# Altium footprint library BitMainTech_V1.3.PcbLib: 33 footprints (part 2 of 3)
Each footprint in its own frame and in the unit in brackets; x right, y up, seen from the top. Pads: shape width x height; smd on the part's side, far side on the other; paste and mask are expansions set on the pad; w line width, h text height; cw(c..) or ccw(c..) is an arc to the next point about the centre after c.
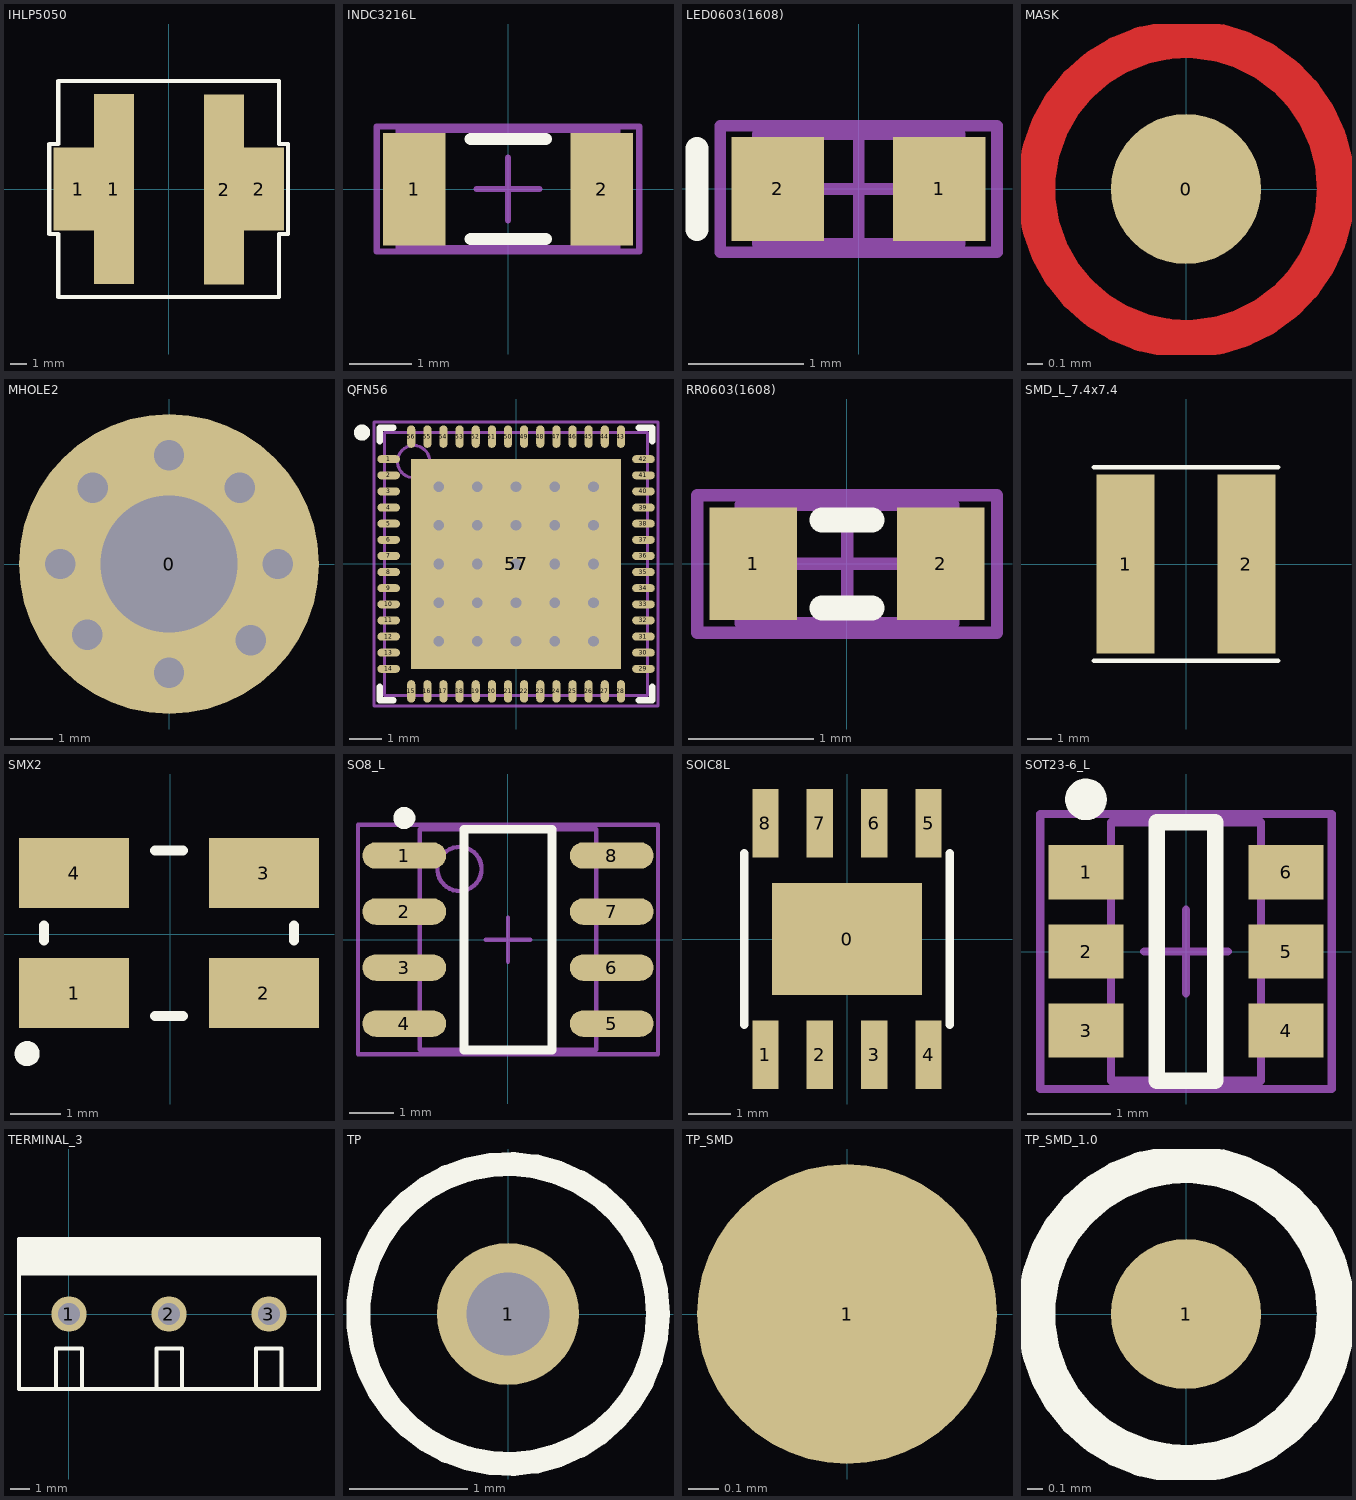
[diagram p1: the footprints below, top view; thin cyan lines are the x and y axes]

## IHLP5050 [mm]
height 18.15
pads (4):
  rect 2.945x4.95 smd: 1(-5.407,0) 2(5.407,0)
  rect 2.388x11.328 smd: 1(-3.28,0) 2(3.32,-0.03)
Top Overlay:
  lines w0.254: -7.137,-2.688 -6.6,-2.688 -6.6,-3.225 -6.6,-6.45 6.6,-6.45 6.6,-3.225 6.6,-2.688 7.137,-2.688 7.137,2.688 6.6,2.688 6.6,3.225 6.6,6.45 -6.6,6.45 -6.6,3.225 -6.6,2.688 -7.137,2.688 -7.137,-2.688
Top Paste:
  rectangle: 2.134,-5.664 4.521,5.664
  rectangle: -4.521,-5.664 -2.134,5.664
Top Solder:
  rectangle: 2.134,-5.664 4.521,5.664
  rectangle: -4.521,-5.664 -2.134,5.664
3D body: height 6.5, standoff 0, extent -6.6,-6.449 6.6,6.449

## INDC3216L [mm] "Chip Inductor, Body 3.2x1.6mm, IPC High Density"
height 1.9
pads (2):
  rect 1x1.8 smd: 1(-1.5,0) 2(1.5,0)
Top Overlay:
  lines w0.2: -0.6,-0.8 0.6,-0.8 ; -0.6,0.8 0.6,0.8
Mechanical 13:
  lines w0.1: -1.75,-0.95 1.75,-0.95 1.75,0.95 -1.75,0.95 -1.75,-0.95
Mechanical 15:
  lines w0.1: -0.5,0 0.5,0 ; 0,-0.5 0,0.5 ; -2.1,-1 2.1,-1 2.1,1 -2.1,1 -2.1,-1
3D body: height 1.9, standoff 0, extent -1.75,-0.95 1.75,0.95

## LED0603(1608) [mm] "Chip LED, Body 1.6x0.8mm, IPC High Density"
height 18.15
pads (2):
  rect 0.8x0.9 smd: 1(0.7,0) 2(-0.7,0)
Top Overlay:
  lines w0.2: -1.4,-0.35 -1.4,0.35
Mechanical 13:
  lines w0.1: -0.875,-0.475 0.875,-0.475 0.875,0.475 -0.875,0.475 -0.875,-0.475
Mechanical 15:
  lines w0.1: -0.475,0 0.475,0 ; 0,-0.475 0,0.475 ; -1.2,-0.55 1.2,-0.55 1.2,0.55 -1.2,0.55 -1.2,-0.55
3D body: height 0.85, standoff 0, extent -0.875,-0.475 0.875,0.475

## MASK [mm] "SMD MASK 1mm"
height 18.15
pads (1):
  round 1 smd: 0(0,0)
Top Layer:
  circle w0.254: c0,0 r1
Top Paste:
  circle w1.5: c0,0 r0.508
  circle w0.254: c0,0 r0.508
Top Solder:
  circle w1: c0,0 r0.762

## MHOLE2 [mm]
height 0.9
pads (1):
  round 7 hole 3.2 unplated: 0(0,0)
via 1.905,-1.778 diameter 1.27 hole 0.711
via 1.651,1.778 diameter 1.27 hole 0.711
via -1.778,1.778 diameter 1.27 hole 0.711
via -1.905,-1.651 diameter 1.27 hole 0.711
via 0,-2.54 diameter 1.27 hole 0.711
via -2.54,0 diameter 1.27 hole 0.711
via 2.54,0 diameter 1.27 hole 0.711
via 0,2.54 diameter 1.27 hole 0.711

## QFN56 [mm]
height 18.15
pads (58):
  oval 0.7x0.25 smd: 1(-3.95,3.25) 2(-3.95,2.75) 3(-3.95,2.25) 4(-3.95,1.75) 5(-3.95,1.25) 6(-3.95,0.75) 7(-3.95,0.25) 8(-3.95,-0.25) 9(-3.95,-0.75) 10(-3.95,-1.25) 11(-3.95,-1.75) 12(-3.95,-2.25) 13(-3.95,-2.75) 14(-3.95,-3.25) 29(3.95,-3.25) 30(3.95,-2.75) 31(3.95,-2.25) 32(3.95,-1.75) 33(3.95,-1.25) 34(3.95,-0.75) 35(3.95,-0.25) 36(3.95,0.25) 37(3.95,0.75) 38(3.95,1.25) 39(3.95,1.75) 40(3.95,2.25) 41(3.95,2.75) 42(3.95,3.25)
  oval 0.25x0.7 smd: 15(-3.25,-3.95) 16(-2.75,-3.95) 17(-2.25,-3.95) 18(-1.75,-3.95) 19(-1.25,-3.95) 20(-0.75,-3.95) 21(-0.25,-3.95) 22(0.25,-3.95) 23(0.75,-3.95) 24(1.25,-3.95) 25(1.75,-3.95) 26(2.25,-3.95) 27(2.75,-3.95) 28(3.25,-3.95) 43(3.25,3.95) 44(2.75,3.95) 45(2.25,3.95) 46(1.75,3.95) 47(1.25,3.95) 48(0.75,3.95) 49(0.25,3.95) 50(-0.25,3.95) 51(-0.75,3.95) 52(-1.25,3.95) 53(-1.75,3.95) 54(-2.25,3.95) 55(-2.75,3.95) 56(-3.25,3.95)
  rect 6.5x6.5 smd: 57(0,0)
  rect 6.5x6.5 smd far side: 57(0,0)
via -2.4,2.4 diameter 0.66 hole 0.33
via -1.2,2.4 diameter 0.66 hole 0.33
via 0,2.4 diameter 0.66 hole 0.33
via 1.2,2.4 diameter 0.66 hole 0.33
via 2.4,2.4 diameter 0.66 hole 0.33
via -2.4,1.2 diameter 0.66 hole 0.33
via -1.2,1.2 diameter 0.66 hole 0.33
via 0,1.2 diameter 0.66 hole 0.33
via 1.2,1.2 diameter 0.66 hole 0.33
via 2.4,1.2 diameter 0.66 hole 0.33
via -2.4,0 diameter 0.66 hole 0.33
via -1.2,0 diameter 0.66 hole 0.33
via 0,0 diameter 0.66 hole 0.33
via 1.2,0 diameter 0.66 hole 0.33
via 2.4,0 diameter 0.66 hole 0.33
via -2.4,-1.2 diameter 0.66 hole 0.33
via -1.2,-1.2 diameter 0.66 hole 0.33
via 0,-1.2 diameter 0.66 hole 0.33
via 1.2,-1.2 diameter 0.66 hole 0.33
via 2.4,-1.2 diameter 0.66 hole 0.33
via -2.4,-2.4 diameter 0.66 hole 0.33
via -1.2,-2.4 diameter 0.66 hole 0.33
via 0,-2.4 diameter 0.66 hole 0.33
via 1.2,-2.4 diameter 0.66 hole 0.33
via 2.4,-2.4 diameter 0.66 hole 0.33
Top Overlay:
  circle w0.25: c-4.775,4.075 r0.125
  lines w0.2: -4.225,-3.8 -4.225,-4.225 -3.8,-4.225 ; -4.225,3.8 -4.225,4.225 -3.8,4.225 ; 3.8,-4.225 4.225,-4.225 4.225,-3.8 ; 3.8,4.225 4.225,4.225 4.225,3.8
Mechanical 13:
  circle w0.1: c-3.175,3.175 r0.5
  lines w0.1: -4.075,-4.075 -4.075,4.075 4.075,4.075 4.075,-4.075 -4.075,-4.075
Mechanical 15:
  lines w0.1: -0.5,0 0.5,0 ; 0,-0.5 0,0.5 ; -4.4,-4.4 -4.4,4.4 4.4,4.4 4.4,-4.4 -4.4,-4.4
3D body: height 0.9, standoff 0, extent -4.075,-4.075 4.075,4.075

## RR0603(1608) [mm] "Chip Resistor, Body 1.6x0.8mm, IPC High Density"
height 0.6
pads (2):
  rect 0.7x0.9 smd: 1(-0.75,0) 2(0.75,0)
Top Overlay:
  lines w0.2: -0.2,-0.35 0.2,-0.35 ; -0.2,0.35 0.2,0.35
Mechanical 13:
  lines w0.1: -0.85,-0.475 -0.85,0.475 0.85,0.475 0.85,-0.475 -0.85,-0.475
Mechanical 15:
  lines w0.1: -0.475,0 0.475,0 ; 0,-0.475 0,0.475 ; -1.2,-0.55 -1.2,0.55 1.2,0.55 1.2,-0.55 -1.2,-0.55
3D body: height 0.6, standoff 0, extent -0.85,-0.475 0.85,0.475

## SMD_L_7.4x7.4 [mm]
height 18.15
pads (2):
  rect 2.4x7.4 smd: 1(-2.5,0) 2(2.5,0)
Top Overlay:
  lines w0.203: -3.8,-4 3.8,-4 ; -3.8,4 3.8,4

## SMX2 [mm]
height 0.9
pads (4):
  rect 2.2x1.4 smd: 1(-1.925,-1.175) 2(1.875,-1.175) 3(1.875,1.225) 4(-1.925,1.225)
Top Overlay:
  circle w0.25: c-2.862,-2.384 r0.125
  lines w0.2: -2.525,-0.125 -2.525,0.175 ; -0.304,-1.628 0.254,-1.628 ; -0.304,1.678 0.254,1.678 ; 2.475,-0.125 2.475,0.175

## SO8_L [mm] "SOIC, 8-Leads, Body 4.9x3.9mm, Pitch 1.27mm, IPC High Density"
height 1.75
pads (8):
  oval 1.9x0.6 smd: 1(-2.35,1.905) 2(-2.35,0.635) 3(-2.35,-0.635) 4(-2.35,-1.905) 5(2.35,-1.905) 6(2.35,-0.635) 7(2.35,0.635) 8(2.35,1.905)
Top Overlay:
  circle w0.25: c-2.35,2.755 r0.125
  lines w0.2: -1,-2.5 1,-2.5 1,2.5 -1,2.5 -1,-2.5
Mechanical 13:
  circle w0.1: c-1.1,1.6 r0.5
  lines w0.1: -2,-2.5 2,-2.5 2,2.5 -2,2.5 -2,-2.5
Mechanical 15:
  lines w0.1: -0.5,0 0.5,0 ; 0,-0.5 0,0.5 ; -3.4,-2.6 3.4,-2.6 3.4,2.6 -3.4,2.6 -3.4,-2.6
3D body: height 1.75, standoff 0, extent -2,-2.5 2,2.5

## SOIC8L [mm]
pads (9):
  rect 3.51x2.62 smd: 0(0,0)
  rect 0.61x1.6 smd: 1(-1.905,-2.7) 2(-0.635,-2.7) 3(0.635,-2.7) 4(1.905,-2.7) 5(1.905,2.7) 6(0.635,2.7) 7(-0.635,2.7) 8(-1.905,2.7)
Top Overlay:
  lines w0.203: -2.4,-2 -2.4,2 ; 2.4,-2 2.4,2

## SOT23-6_L [mm] "SOT23, 6-Leads, Body 2.9x1.6mm, Pitch 0.95mm, Lead Span 2.7mm, IPC High Density"
height 1.45
pads (6):
  rect 0.9x0.65 smd: 1(-1.2,0.95) 2(-1.2,0) 3(-1.2,-0.95) 4(1.2,-0.95) 5(1.2,0) 6(1.2,0.95)
Top Overlay:
  circle w0.25: c-1.2,1.825 r0.125
  lines w0.2: -0.35,-1.55 -0.35,1.55 0.35,1.55 0.35,-1.55 -0.35,-1.55
Mechanical 13:
  lines w0.1: -0.9,-1.55 0.9,-1.55 0.9,1.55 -0.9,1.55 -0.9,-1.55
Mechanical 15:
  lines w0.1: -0.5,0 0.5,0 ; 0,-0.5 0,0.5 ; -1.75,-1.65 1.75,-1.65 1.75,1.65 -1.75,1.65 -1.75,-1.65
3D body: height 1.45, standoff 0, extent -0.9,-1.55 0.9,1.55

## TERMINAL_3 [mm]
height 9.8
pads (3):
  round 1.8 hole 1.1: 1(0,0) 2(5.08,0) 3(10.16,0)
Top Overlay:
  rectangle: -2.54,1.95 12.7,3.81
  lines w0.203: -0.65,-3.81 -0.65,-1.75 0.65,-1.75 0.65,-3.81 ; 4.45,-3.81 4.45,-1.75 5.75,-1.75 5.75,-3.81 ; 9.5,-3.81 9.5,-1.75 10.8,-1.75 10.8,-3.81 ; -2.54,-3.81 -2.54,3.81 12.7,3.81 12.7,-3.81 -2.54,-3.81

## TP [mm]
height 18.15
pads (1):
  round 1.2 hole 0.7: 1(0,0)
Top Overlay:
  circle w0.203: c0,0 r1.27

## TP_SMD [mm]
height 18.15
pads (1):
  round 1 smd: 1(0,0)

## TP_SMD_1.0 [mm]
pads (1):
  round 1 smd: 1(0,0)
Top Overlay:
  circle w0.254: c0,0 r1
